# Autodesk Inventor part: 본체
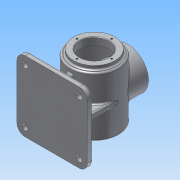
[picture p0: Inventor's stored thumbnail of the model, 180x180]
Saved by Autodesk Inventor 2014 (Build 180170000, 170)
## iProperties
Created: 2015-07
Part Number: 본체
Material: 알루미늄 6061
Document SubType Name: Modeling
Designer: net
Density: 2.71 g/cm^3
Appearance: 알루미늄 - 평지
Mass: 1277.62 g
Surface Area: 1267.64 cm^2
Volume: 471.447 cm^3
Author: net
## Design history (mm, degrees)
sketch "스케치1"
  geometry: C1 r 45 at (0, 0); 1 further point
  constraints: 1 centre point, 1 coincident
  dimensions: "d0" = 90 diameter of C1
extrude "돌출1" new body sketch "스케치1" stored distance "d1" = 110; taper "d2" = 0 deg
sketch "스케치2"
  geometry: C1 r 45 at (0, 0) reference; C2 r 38 at (0, 0)
  constraints: 1 centre point, 1 coincident
  dimensions: "d3" = 76 diameter of C2
extrude "돌출2" join sketch "스케치2" distance "d4" = 7; taper "d5" = 0 deg
node "작업 평면1"
sketch "스케치3"
  geometry: L1 (45, 5)-(-45, 5); L2 (-45, 5)-(-45, -5); L3 (-45, -5)-(45, -5); L4 (45, -5)-(45, 5); L5 (5, 45)-(-5, 45); L6 (-5, 45)-(-5, -45); L7 (-5, -45)-(5, -45); L8 (5, -45)-(5, 45); 5 further points
  constraints: 16 end point, 4 midpoint, 4 parallel, 2 horizontal, 2 horizontal alignment, 2 perpendicular, 2 vertical alignment
  dimensions: "d7" = 10 distance of L3.end L1.start; "d8" = 10 distance of L6.end L7.end; "d9" = 90 distance of L7.end L5.start; "d10" = 90 distance of L1.start L1.end
extrude "돌출3" join sketch "스케치3" stored distance "d11" = 7; taper "d12" = 0 deg
sketch "스케치4"
  geometry: L1 (-65, 65)-(65, 65); L2 (65, 65)-(65, -65); L3 (65, -65)-(-65, -65); L4 (-65, -65)-(-65, 65); 3 further points
  constraints: 8 end point, 2 midpoint, 2 parallel, 1 horizontal, 1 horizontal alignment, 1 perpendicular, 1 vertical alignment
  dimensions: "d13" = 130 distance of L1.start L1.end; "d14" = 130 distance of L1.end L2.end
extrude "돌출4" join sketch "스케치4" distance "d15" = 10; taper "d16" = 0 deg
hole "구멍1" diameter "d19" = 54; stored, may be unused: countersink angle "d23" = 90 deg, drill point angle "d25" = 0 deg; dims "d17" = 10, "d18" = 10, "d20" = 6, "d21" = 4, "d22" = 2, "d24" = 14
hole "구멍2" diameter "d28" = 80; stored, may be unused: countersink angle "d32" = 90 deg, drill point angle "d34" = 0 deg; dims "d26" = 10, "d27" = 10, "d29" = 6, "d30" = 4, "d31" = 2, "d33" = 96
node "작업 평면2"
sketch "스케치5"
  geometry: C1 r 38 at (0, 0); 1 further point
  constraints: 1 centre point, 1 coincident
  dimensions: "d36" = 76 diameter of C1
extrude "돌출5" join sketch "스케치5" stored distance "d37" = 10; taper "d38" = 0 deg
hole "구멍3" diameter "d41" = 54; stored, may be unused: countersink angle "d45" = 90 deg, drill point angle "d47" = 0 deg; dims "d39" = 10, "d40" = 10, "d42" = 6, "d43" = 4, "d44" = 2, "d46" = 50
sketch "스케치6"
  geometry: C1 r 7.5 at (-50, 50); C2 r 7.5 at (50, 50); C3 r 7.5 at (50, -50); C4 r 7.5 at (-50, -50); 1 further point
  constraints: 4 centre point, 3 equal radius, 2 horizontal alignment, 2 vertical alignment
  dimensions: "d48" = 100 distance of C2.centre C1.centre; "d49" = 50 horizontal distance of point (0, 0) C1.centre; "d50" = 15 diameter of C4; "d51" = 100 distance of C4.centre C1.centre; "d52" = 50 horizontal distance of point (0, 0) C4.centre
extrude "돌출6" join sketch "스케치6" distance "d53" = 3; taper "d54" = 0 deg
sketch "스케치7"
  geometry: C1 r 27 at (0, 0) reference; 1 further point
  constraints: 1 vertical alignment
  dimensions: "d55" = 32 distance of C1.centre point (0, 32)
hole "구멍4" sketch "스케치7" at (0, 32) diameter "d56" = 3.242; stored, may be unused: countersink angle "d60" = 90 deg, drill point angle "d62" = 118 deg; dims "d57" = 8, "d58" = 4, "d59" = 2, "d61" = 10
sketch "스케치8"
  geometry: C1 r 27 at (0, 0) reference; 1 further point
  constraints: 1 vertical alignment
  dimensions: "d66" = 32 distance of C1.centre point (0, 32)
hole "구멍5" sketch "스케치8" at (0, 32) diameter "d67" = 3.242; stored, may be unused: countersink angle "d71" = 90 deg, drill point angle "d73" = 118 deg; dims "d68" = 8, "d69" = 4, "d70" = 2, "d72" = 10
sketch "스케치9"
  geometry: C1 r 7.5 at (0, 0) reference; C2 r 7.5 at (100, 0) reference; C3 r 7.5 at (100, -100) reference; C4 r 7.5 at (0, -100) reference; C5 r 5 at (0, 0); C6 r 5 at (100, 0); C7 r 5 at (100, -100); C8 r 5 at (0, -100); 1 further point
  constraints: 4 centre point, 4 coincident, 3 equal radius
  dimensions: "d77" = 10 diameter of C5
extrude "돌출7" cut sketch "스케치9" distance "d78" = 20; taper "d79" = 0 deg
fillet "모깎기1" dims "d80" = 15, "d81" = 3
fillet "모깎기2" dims "d82" = 3
fillet "모깎기3" dims "d83" = 3
fillet "모깎기4" dims "d84" = 3
fillet "모깎기5" dims "d85" = 3
sketch "스케치10"
  geometry: C1 r 42 at (0, 0) reference; 1 further point
  constraints: 1 coincident, 1 other
feature "엠보싱1" sketch "스케치10" dims "d86" = 0.5, "d87" = 0
chamfer "모따기1" distance "d88" = 1; stored, may be unused: second distance "d89" = 2, angle "d90" = 45 deg
fillet "모깎기6" dims "d91" = 3
node "솔리드1"
pattern_circular "원형 패턴1" dims angle "d64" = 360 deg
pattern_circular "원형 패턴2" dims angle "d75" = 360 deg
node "투영된 루프1"
node "투영된 루프2"
node "투영된 루프3"
other parameters: "d6" = -78, "d35" = 62
